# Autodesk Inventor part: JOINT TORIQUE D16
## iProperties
Created: 2004-11
Part Number: JOINT TORIQUE D16
Document SubType Name: Modeling
Designer: Bruno
Manufacturer: Standard
Standards Organization: Custom
Author: Bruno
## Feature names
1. Base1
